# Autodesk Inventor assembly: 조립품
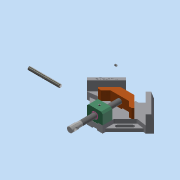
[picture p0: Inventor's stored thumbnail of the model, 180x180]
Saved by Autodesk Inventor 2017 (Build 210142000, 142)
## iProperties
Part Number: 조립품
Material: 일반
Document SubType Name: Assembly
Designer: mrc
Author: mrc
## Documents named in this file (11)
- C:\Users\mrc\Desktop\700506V1011\조립품.iam
- C:\Users\mrc\Desktop\700506V1011\본체.ipt
- C:\Users\mrc\Desktop\700506V1011\리드스크류.ipt
- C:\Users\mrc\Desktop\700506V1011\멈춤나사 M4x5.ipt
- C:\Users\mrc\Desktop\700506V1011\멈춤나사 M4x10.ipt
- C:\Users\mrc\Desktop\700506V1011\볼트 M4x16.ipt
- C:\Users\mrc\Desktop\700506V1011\부시.ipt
- C:\Users\mrc\Desktop\700506V1011\서포트.ipt
- C:\Users\mrc\Desktop\700506V1011\조.ipt
- C:\Users\mrc\Desktop\700506V1011\평행 핀 2.5x24.ipt
- C:\Users\mrc\Desktop\700506V1011\핸들.ipt
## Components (1 placed, 1 different names)
1. 핸들:1
